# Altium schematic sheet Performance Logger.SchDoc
size Letter; Origin: Eagle
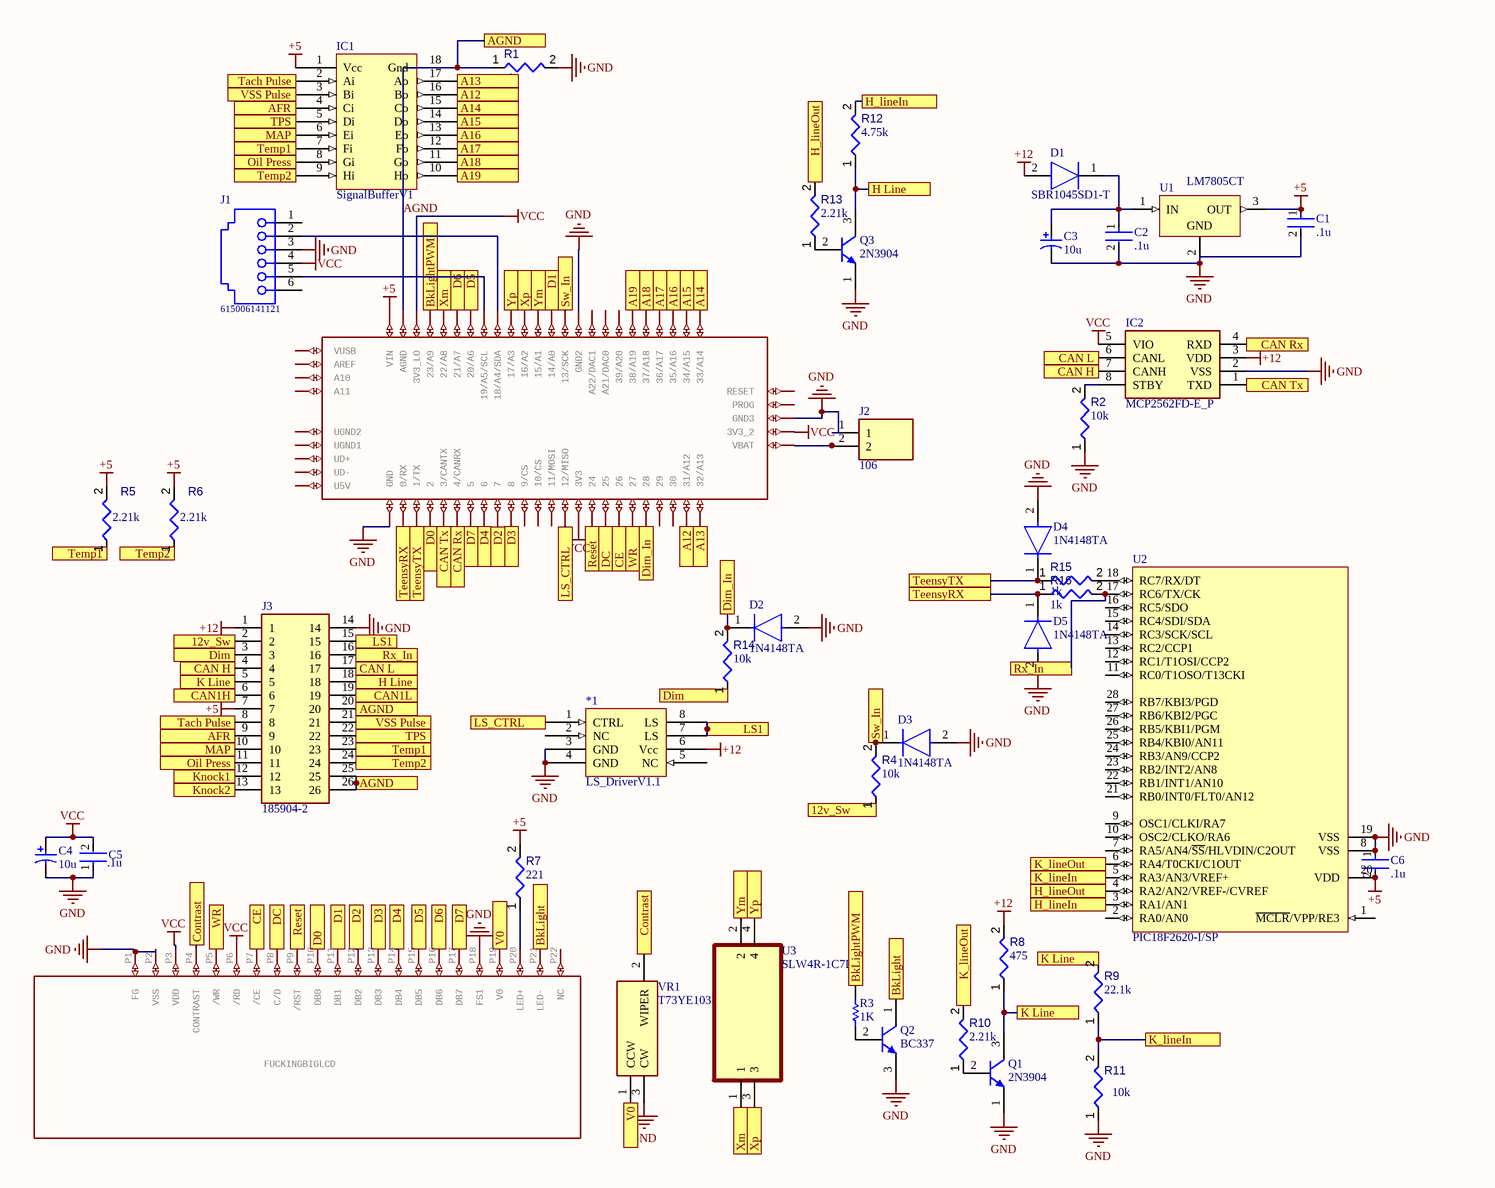
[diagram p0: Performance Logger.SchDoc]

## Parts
*1  LS_DriverV1.1  [LS_DriverV1.1]
C1  .1u  [FP-K105Z20Y5VF5TL2-MFG]
C2  .1u  [FP-K105Z20Y5VF5TL2-MFG]
C3  10u  [CAPPR55-200-1100X500X1200]
C4  10u  [CAPPR55-200-1100X500X1200]
C5  .1u  [FP-K105Z20Y5VF5TL2-MFG]
C6  .1u  [FP-K105Z20Y5VF5TL2-MFG]
D1  SBR1045SD1-T  [DO-201AD]
D2  1N4148TA  [FP-017AG-MFG]
D3  1N4148TA  [FP-017AG-MFG]
D4  1N4148TA  [FP-017AG-MFG]
D5  1N4148TA  [FP-017AG-MFG]
FUCKINGBIGLCD  BIIIGGG_DEVICE  [BIIIGGG_FOOTPRINT]  (value not drawn)
IC1  SignalBufferV1  [DIP18]
IC2  MCP2562FD-E_P  [DIP781W56P254L950H533Q8N]
J1  615006141121  [615006141121]
J2  106  [106_1]
J3  185904-2  [1859042]
Q1  2N3904  [ONSC-TO-92-3-29-11]
Q2  BC337  [ONSC-TO-92-3-29-11]
Q3  2N3904  [ONSC-TO-92-3-29-11]
R1  value 1k  [RESA60-630X240]  (hidden comment: MFR-25FBF52-1K)
R2  value 10k  [RESA60-630X240]  (hidden comment: MFR-25FBF52-10K)
R3  1K  [RESA60-630X240]
R4  value 10k  [RESA60-630X240]  (hidden comment: MFR-25FBF52-10K)
R5  value 2.21k  [RESA60-630X240]  (hidden comment: MFR-25FBF52-2K21)
R6  value 2.21k  [RESA60-630X240]  (hidden comment: MFR-25FBF52-2K21)
R7  value 221  [RESA60-630X240]  (hidden comment: MFR-25FBF52-221R)
R8  value 475  [RESA60-630X240]  (hidden comment: MFR-25FBF52-475R)
R9  value 22.1k  [RESA60-630X240]  (hidden comment: MFR-25FBF52-22K1)
R10  value 2.21k  [RESA60-630X240]  (hidden comment: MFR-25FBF52-2K21)
R11  value 10k  [RESA60-630X240]  (hidden comment: MFR-25FBF52-10K)
R12  value 4.75k  [RESA60-630X240]  (hidden comment: MFR-25FBF52-4K75)
R13  value 2.21k  [RESA60-630X240]  (hidden comment: MFR-25FBF52-2K21)
R14  value 10k  [RESA60-630X240]  (hidden comment: MFR-25FBF52-10K)
R15  value 1k  [RESA60-630X240]  (hidden comment: MFR-25FBF52-1K)
R16  value 1k  [RESA60-630X240]  (hidden comment: MFR-25FBF52-1K)
U1  LM7805CT  [FAIR-TO-220-3]
U2  PIC18F2620-I/SP  [SPDIP300-SP28]
U3  SLW4R-1C7LF  [FCI_SLW4R-1C7LF]
U$1  TEENSY_3.5/3.6  [TEENSY_3.5/3.6]  (value not drawn)
VR1  T73YE103KT20  [T73YE103KT20]

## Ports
12v_Sw, A12, A13, A14, A15, A16, A17, A18, A19, AFR, AGND, BkLight, BkLightPWM, CAN1H, CAN1L, CAN H, CAN L, CAN Rx, CAN Tx, CE, Contrast, D0 (in), D1, D2, D3, D4, D5, D6, D7, DC, Dim, Dim_In, H Line, H_lineIn, H_lineOut, K Line, K_lineIn, K_lineOut, Knock1, Knock2, LS1, LS_CTRL, MAP, Oil Press, Reset, Rx_In, Sw_In, Tach Pulse, TeensyRX, TeensyTX, Temp1, Temp2, TPS, V0, VSS Pulse, WR, Xm, Xp, Ym, Yp

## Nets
+5: C1.1 C6.2 IC1.1(Vcc) J3.7 R5.2 R6.2 R7.2 U1.3(OUT) U2.20(VDD) U$1.VIN
+12: *1.6(Vcc) D1.2(A) IC2.3(VDD) J3.1 R8.2
GND: *1.3(GND) *1.4(GND) C1.2 C2.2 C3.2 C4.2 C5.1 C6.1 D2.2(A) D3.2(A) D4.2(A) D5.2(A) FUCKINGBIGLCD.P1(FG) FUCKINGBIGLCD.P2(VSS) FUCKINGBIGLCD.P18(FS1) IC2.2(VSS) J1.3 J2.1 J3.14 Q1.1(E) Q2.3(E) Q3.1(E) R1.2 R2.1 R11.1 U1.2(GND) U2.8(VSS) U2.19(VSS) U$1.GND U$1.GND2 U$1.GND3 VR1.3(CW)
VCC: C4.1 C5.2 FUCKINGBIGLCD.P3(VDD) FUCKINGBIGLCD.P6(/RD) IC2.5(VIO) J1.4 U$1.3V3 U$1.3V3_2 U$1.3V3_LO
12v_Sw: J3.2 R4.1 ; port 12v_Sw
A12: IC1.16(Bo) U$1.31/A12 ; port A12
A13: IC1.17(Ao) U$1.32/A13 ; port A13
A14: IC1.15(Co) U$1.33/A14 ; port A14
A15: IC1.14(Do) U$1.34/A15 ; port A15
A16: IC1.13(Eo) U$1.35/A16 ; port A16
A17: IC1.12(Fo) U$1.36/A17 ; port A17
A18: IC1.11(Go) U$1.37/A18 ; port A18
A19: IC1.10(Ho) U$1.38/A19 ; port A19
AFR: IC1.4(Ci) J3.9 ; port AFR
AGND: IC1.18(Gnd) J3.20 J3.25 J3.26 R1.1 U$1.AGND ; port AGND
BkLight: FUCKINGBIGLCD.P21(LED-) Q2.1(C) ; port BkLight
BkLightPWM: R3.2 U$1.23/A9 ; port BkLightPWM
CAN1H: J3.6 ; port CAN1H
CAN1L: J3.19 ; port CAN1L
CAN H: IC2.7(CANH) J3.4 ; port CAN H
CAN L: IC2.6(CANL) J3.17 ; port CAN L
CAN Rx: IC2.4(RXD) U$1.4/CANRX ; port CAN Rx
CAN Tx: IC2.1(TXD) U$1.3/CANTX ; port CAN Tx
CE: FUCKINGBIGLCD.P7(/CE) U$1.26 ; port CE
Contrast: FUCKINGBIGLCD.P4(CONTRAST) VR1.2(WIPER) ; port Contrast
D0: FUCKINGBIGLCD.P10(DB0) U$1.2 ; port D0
D1: FUCKINGBIGLCD.P11(DB1) U$1.14/A0 ; port D1
D2: FUCKINGBIGLCD.P12(DB2) U$1.7 ; port D2
D3: FUCKINGBIGLCD.P13(DB3) U$1.8 ; port D3
D4: FUCKINGBIGLCD.P14(DB4) U$1.6 ; port D4
D5: FUCKINGBIGLCD.P15(DB5) U$1.20/A6 ; port D5
D6: FUCKINGBIGLCD.P16(DB6) U$1.21/A7 ; port D6
D7: FUCKINGBIGLCD.P17(DB7) U$1.5 ; port D7
DC: FUCKINGBIGLCD.P8(C/D) U$1.25 ; port DC
Dim: J3.3 R14.1 ; port Dim
Dim_In: D2.1(C) R14.2 U$1.28 ; port Dim_In
H Line: J3.18 Q3.3(C) R12.1 ; port H Line
H_lineIn: R12.2 U2.3(RA1/AN1) ; port H_lineIn
H_lineOut: R13.2 U2.4(RA2/AN2/VREF-/CVREF) ; port H_lineOut
K Line: J3.5 Q1.3(C) R8.1 R9.2 ; port K Line
K_lineIn: R9.1 R11.2 U2.5(RA3/AN3/VREF+) ; port K_lineIn
K_lineOut: R10.2 U2.6(RA4/T0CKI/C1OUT) ; port K_lineOut
Knock1: J3.12 ; port Knock1
Knock2: J3.13 ; port Knock2
LS1: *1.7(LS) *1.8(LS) J3.15 ; port LS1
LS_CTRL: *1.1(CTRL) U$1.12/MISO ; port LS_CTRL
MAP: IC1.6(Ei) J3.10 ; port MAP
Oil Press: IC1.8(Gi) J3.11 ; port Oil Press
Reset: FUCKINGBIGLCD.P9(/RST) U$1.24 ; port Reset
Rx_In: J3.16 R16.2 U2.17(RC6/TX/CK) ; port Rx_In
Sw_In: D3.1(C) R4.2 U$1.13/SCK ; port Sw_In
Tach Pulse: IC1.2(Ai) J3.8 ; port Tach Pulse
TeensyRX: D5.1(C) R16.1 U$1.0/RX ; port TeensyRX
TeensyTX: D4.1(C) R15.1 U$1.1/TX ; port TeensyTX
Temp1: IC1.7(Fi) J3.23 R5.1 ; port Temp1
Temp2: IC1.9(Hi) J3.24 R6.1 ; port Temp2
TPS: IC1.5(Di) J3.22 ; port TPS
V0: FUCKINGBIGLCD.P19(V0) VR1.1(CCW) ; port V0
VSS Pulse: IC1.3(Bi) J3.21 ; port VSS Pulse
WR: FUCKINGBIGLCD.P5(/WR) U$1.27 ; port WR
Xm: U3.1 U$1.22/A8 ; port Xm
Xp: U3.3 U$1.16/A2 ; port Xp
Ym: U3.2 U$1.15/A1 ; port Ym
Yp: U3.4 U$1.17/A3 ; port Yp
NetC2_1: C2.1 C3.1 D1.1(K) U1.1(IN)
NetFUCKINGBIGLCD_P20: FUCKINGBIGLCD.P20(LED+) R7.1
NetIC2_8: IC2.8(STBY) R2.2
NetJ1_2: J1.2 U$1.18/A4/SDA
NetJ1_5: J1.5 U$1.19/A5/SCL
NetJ2_2: J2.2 U$1.VBAT
NetQ1_2: Q1.2(B) R10.1
NetQ2_2: Q2.2(B) R3.1
NetQ3_2: Q3.2(B) R13.1
NetR15_2: R15.2 U2.18(RC7/RX/DT)

Not connected (* = marked no-connect by the designer): *1 2(NC) 5(NC); FUCKINGBIGLCD P22(NC); J1 1 6; U2 1(~{MCLR}/VPP/RE3) 2(RA0/AN0) 7(RA5/AN4/~{SS}/HLVDIN/C2OUT) 9(OSC1/CLKI/RA7) 10(OSC2/CLKO/RA6) 11(RC0/T1OSO/T13CKI) 12(RC1/T1OSI/CCP2) 13(RC2/CCP1) 14(RC3/SCK/SCL) 15(RC4/SDI/SDA) 16(RC5/SDO) 21(RB0/INT0/FLT0/AN12) 22(RB1/INT1/AN10) 23(RB2/INT2/AN8) 24(RB3/AN9/CCP2) 25(RB4/KBI0/AN11) 26(RB5/KBI1/PGM) 27(RB6/KBI2/PGC) 28(RB7/KBI3/PGD); U$1 9/CS 10/CS 11/MOSI 21/DAC0(A21/DAC0) 29 30 39/A20 A10 A11 A22/DAC1 AREF PROG RESET U5V UD+ UD- UGND1 UGND2 VUSB

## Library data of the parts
*1 = CMP-001-0000-1: 10A capable Low side Switch in an 8dip
C1 C2 C5 C6 = CMP-02417-000003-1: CAP CER 1UF 50V Y5V RADIAL; Manufacturer Part Number: K105Z20Y5VF5TL2; Manufacturer: Vishay BC Components; Tolerance: -20+80%; Material: Ceramic
C3 C4 = CMP-1665-00038-2: Aluminum Electrolytic Capacitor, 10 uF, +/- 20%, 50 V, -40 to 85 degC, 2-Pin THD, RoHS, Bulk; Manufacturer: Panasonic; Life (Hours): 2000Hour; Lead/Base Style: Straight; Dissipation Factor: 0.12%; Capacitance: 10uF; Leakage Current: 3uA; Dielectric Material: Aluminium; Lead Diameter: 0.5mm; Voltage Rating: 50V; Ripple Current: 65mA
D1 = SBR1045SD1-T: Diode; Manufacturer_Name: Diodes Inc.
D2-D5 = CMP-07163-000009-1: DIODE GEN PURP 100V 200MA DO35; Manufacturer: ON Semiconductor; Value: 4pF; Max Surge Forward Current: 1A; Max Junction Temp: +175°C; Peak Reverse Current: 5uA
FUCKINGBIGLCD = BIIIGGG_DEVICE: BiggLCD; GateName_1: G$1; SymbolName_1: BIIIGGG_SYMBOL
IC1 = SignalBufferV1-7: Signal Buffer Board
IC2 = MCP2562FD-E_P: Integrated Circuit; Manufacturer_Name: Microchip; Manufacturer_Part_Number: MCP2562FD-E/P
J1 = CMP-1502-01674-1: Modular Jack WR-MJ, Tab Down, Plastic, Horizontal Entry, THT, 6P6C; Manufacturer: Wurth Elektronik; Compliance: Leadfree/RoHS; Contact Resistance: 20mOhm; Port: 1x1; Rated Current: 1.5A; Withstanding Voltage: 1000VAC; Working Voltage: 120VAC
J2 = 106: Connector; Manufacturer_Name: Keystone Electronics
J3 = 185904-2: Connector; Manufacturer_Name: TE Connectivity
Q1 Q3 = CMP-2000-05562-1: General Purpose Transistor, NPN Silicon, 200 mA, 60 V, -55 to 150 degC, 3-Pin TO-92, RoHS, Bulk; Manufacturer: ONSemiconductor; Emitter- Base Voltage VEBO: 6V; Maximum Power Dissipation: 625mW; Maximum DC Collector Current: 0.2A; Collector- Emitter Voltage VCEO Max: 40V; Collector- Base Voltage VCBO: 60V; DC Collector/Base Gain hfe Min: 60; Configuration: Single; Collector-Emitter Saturation Voltage: 0.3V; Gain Bandwidth Product fT: 270MHz
Q2 = CMP-1048-01458-1: Amplifier Transistor, NPN Silicon, 3-Pin TO-92, Bulk Box; Manufacturer: On Semiconductor; Note1: 0; IC Continuous (A): 0.8
R1 R15 R16 = CMP-009-00048-4: Axial Resistor, 1 KOhm, +/- 1%, 250 mW, -55 to 155 degC, 2-Pin THD, RoHS, Bulk; Manufacturer: Yageo; Voltage Rating: 250V; Power: 250mW
R2 R4 R11 R14 = CMP-009-00047-4: Axial Resistor, 10 KOhm, +/- 1%, 0.25 W, -55 to 155 degC, 2-Pin THD, RoHS, Bulk; Manufacturer: Yageo; Power: 250mW; Voltage Rating: 250V
R3 = CMP-1659-00075-1: Axial Resistor, 1 KOhm, +/- 1%, 250 mW, -55 to 155 degC, 2-Pin THD, RoHS, Bulk; Voltage Rating: 250 V; Resistance: 10 kohm; Power Rating: 250 mW
R5 R6 R10 R13 = CMP-009-00054-4: Axial Resistor, 2.21 KOhm, +/- 1%, 0.25 W, -55 to 155 degC, 2-Pin THD, RoHS, Bulk; Manufacturer: Yageo; Voltage Rating: 250V; Power: 250mW
R7 = CMP-009-00051-4: Axial Resistor, 221 Ohm, +/- 1%, 250 mW, -55 to 155 degC, 2-Pin THD, RoHS, Bulk; Manufacturer: Yageo; Power: 250mW; Voltage Rating: 250V
R8 = CMP-009-00056-4: Axial Resistor, 475 Ohm, +/- 1%, 0.25 W, -55 to 155 degC, 2-Pin THD, RoHS, Bulk; Manufacturer: Yageo; Voltage Rating: 250V; Power: 250mW
R9 = CMP-009-00052-4: Axial Resistor, 22.1 KOhm, +/- 1%, 0.25 W, -55 to 155 degC, 2-Pin THD, RoHS, Bulk; Manufacturer: Yageo; Power: 250mW; Voltage Rating: 250V
R12 = CMP-009-00059-4: Axial Resistor, 4.75 KOhm, +/- 1%, 0.25 W, -55 to 155 degC, 2-Pin THD, RoHS, Bulk; Manufacturer: Yageo; Voltage Rating: 250V; Power: 250mW
U1 = CMP-2000-04938-1: Positive Voltage Regulator, 5 V, 1 A, -40 to 125 degC, 3-Pin TO-220, RoHS, Tube; Manufacturer: FairchildSemiconductor; Maximum Input Voltage: 35V; Maximum Quiescent Current: 8mA; Load Regulation: 100mV; Maximum Output Current: 2.2(Typ)A; Output Type: Fixed; Typical Dropout Voltage @ Current: 2@1AV; Rad Hard: No; Output Voltage: 5V; Accuracy: ±4%; Number of Outputs: 1
U2 = CMP-0116-00068-1: Enhanced Flash Microcontroller with 10-Bit A/D and nanoWatt Technology, 64K Flash, 28-Pin PDIP, Industrial Temperature Range
U3 = SLW4R-1C7LF: 4 Position FFC, FPC Connector Contacts, Bottom 0.039 (1.00mm) Through Hole, Right Angle; MF: Amphenol ICC
U$1 = TEENSY_3.5/3.6: GateName_1: G$1
VR1 = T73YE103KT20: Variable Resistor; Manufacturer_Name: Vishay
